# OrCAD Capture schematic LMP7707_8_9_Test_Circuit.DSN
size A; title: LMP7707/LMP7708/LMP7709 Precision, CMOS Input, RRIO,; rev: 1.1; note: Datasheet: SNOSAW5B EVM: N/A
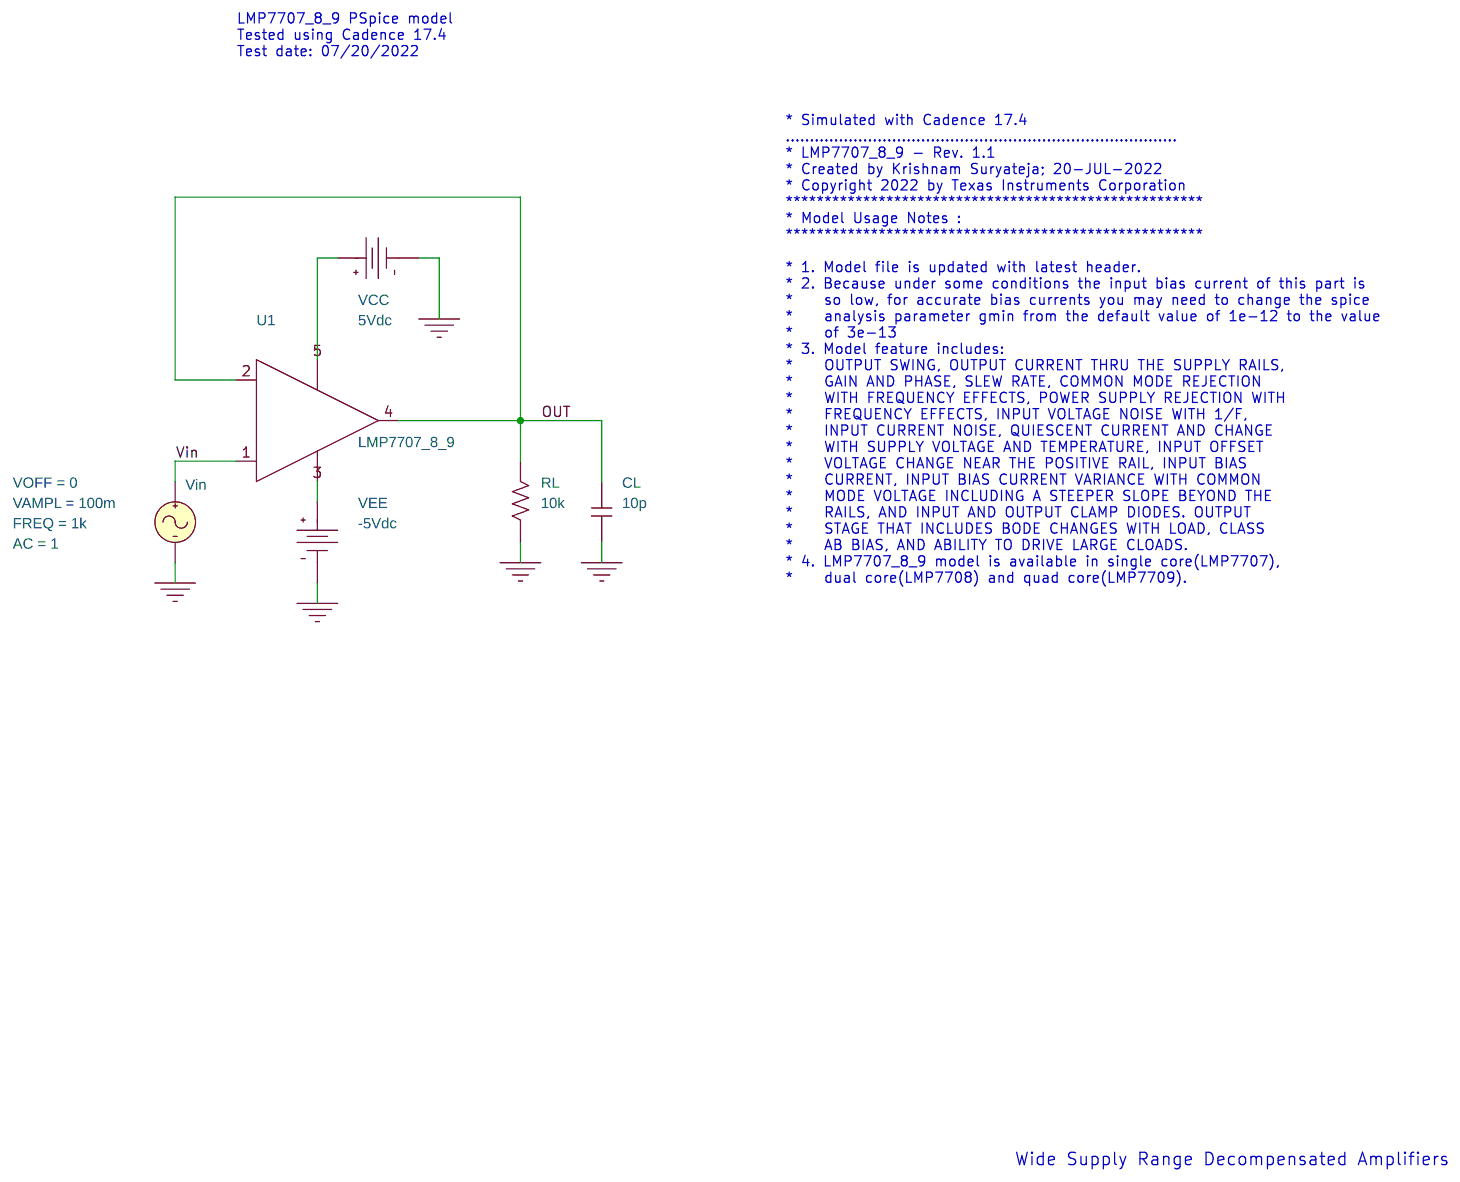
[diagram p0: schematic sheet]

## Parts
CL  10p  [RAD/CK05]
RL  10k  [AX/RC05]
U1  LMP7707_8_9
VCC  VDC
VEE  VDC
Vin  VSIN

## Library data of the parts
CL = C
RL = R
U1 = LMP7707_8_9
VCC = VDC: DC: 5Vdc
VEE = VDC: DC: -5Vdc
Vin = VSIN: AC: 1; FREQ: 1k; VAMPL: 100m; VOFF: 0

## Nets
Vin: U1.1(+) Vin.1(+)
0: CL.1 RL.1 VCC.1(-) VEE.1(-) Vin.2(-)
OUT: CL.2 RL.2 U1.2(-) U1.4(OUT)
N22995: U1.5(V+) VCC.0(+)
N23017: U1.3(V-) VEE.0(+)

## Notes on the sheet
- LMP7707_8_9 PSpice model
  Tested using Cadence 17.4
  Test date: 07/20/2022
- * Simulated with Cadence 17.4
  .................................................................................
  * LMP7707_8_9 - Rev. 1.1
  * Created by Krishnam Suryateja; 20-JUL-2022
  * Copyright 2022 by Texas Instruments Corporation
  ******************************************************
  * Model Usage Notes :
  ******************************************************
  * 1. Model file is updated with latest header.
  * 2. Because under some conditions the input bias current of this part is
  *    so low, for accurate bias currents you may need to change the spice
  *    analysis parameter gmin from the default value of 1e-12 to the value
  *    of 3e-13
  * 3. Model feature includes:
  *    OUTPUT SWING, OUTPUT CURRENT THRU THE SUPPLY RAILS,
  *    GAIN AND PHASE, SLEW RATE, COMMON MODE REJECTION
  *    WITH FREQUENCY EFFECTS, POWER SUPPLY REJECTION WITH
  *    FREQUENCY EFFECTS, INPUT VOLTAGE NOISE WITH 1/F,
  *    INPUT CURRENT NOISE, QUIESCENT CURRENT AND CHANGE
  *    WITH SUPPLY VOLTAGE AND TEMPERATURE, INPUT OFFSET
  *    VOLTAGE CHANGE NEAR THE POSITIVE RAIL, INPUT BIAS
  *    CURRENT, INPUT BIAS CURRENT VARIANCE WITH COMMON
  *    MODE VOLTAGE INCLUDING A STEEPER SLOPE BEYOND THE
  *    RAILS, AND INPUT AND OUTPUT CLAMP DIODES. OUTPUT
  *    STAGE THAT INCLUDES BODE CHANGES WITH LOAD, CLASS
  *    AB BIAS, AND ABILITY TO DRIVE LARGE CLOADS.
  * 4. LMP7707_8_9 model is available in single core(LMP7707),
  *    dual core(LMP7708) and quad core(LMP7709).
- Wide Supply Range Decompensated Amplifiers
